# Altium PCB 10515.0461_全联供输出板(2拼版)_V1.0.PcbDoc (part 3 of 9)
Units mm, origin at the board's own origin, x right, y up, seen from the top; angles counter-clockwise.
Board outline 283.88 x 134.8 mm, 2 copper layers (Top Layer, Bottom Layer); 298 components, 0 nets, 1264 pads, 970 vias.
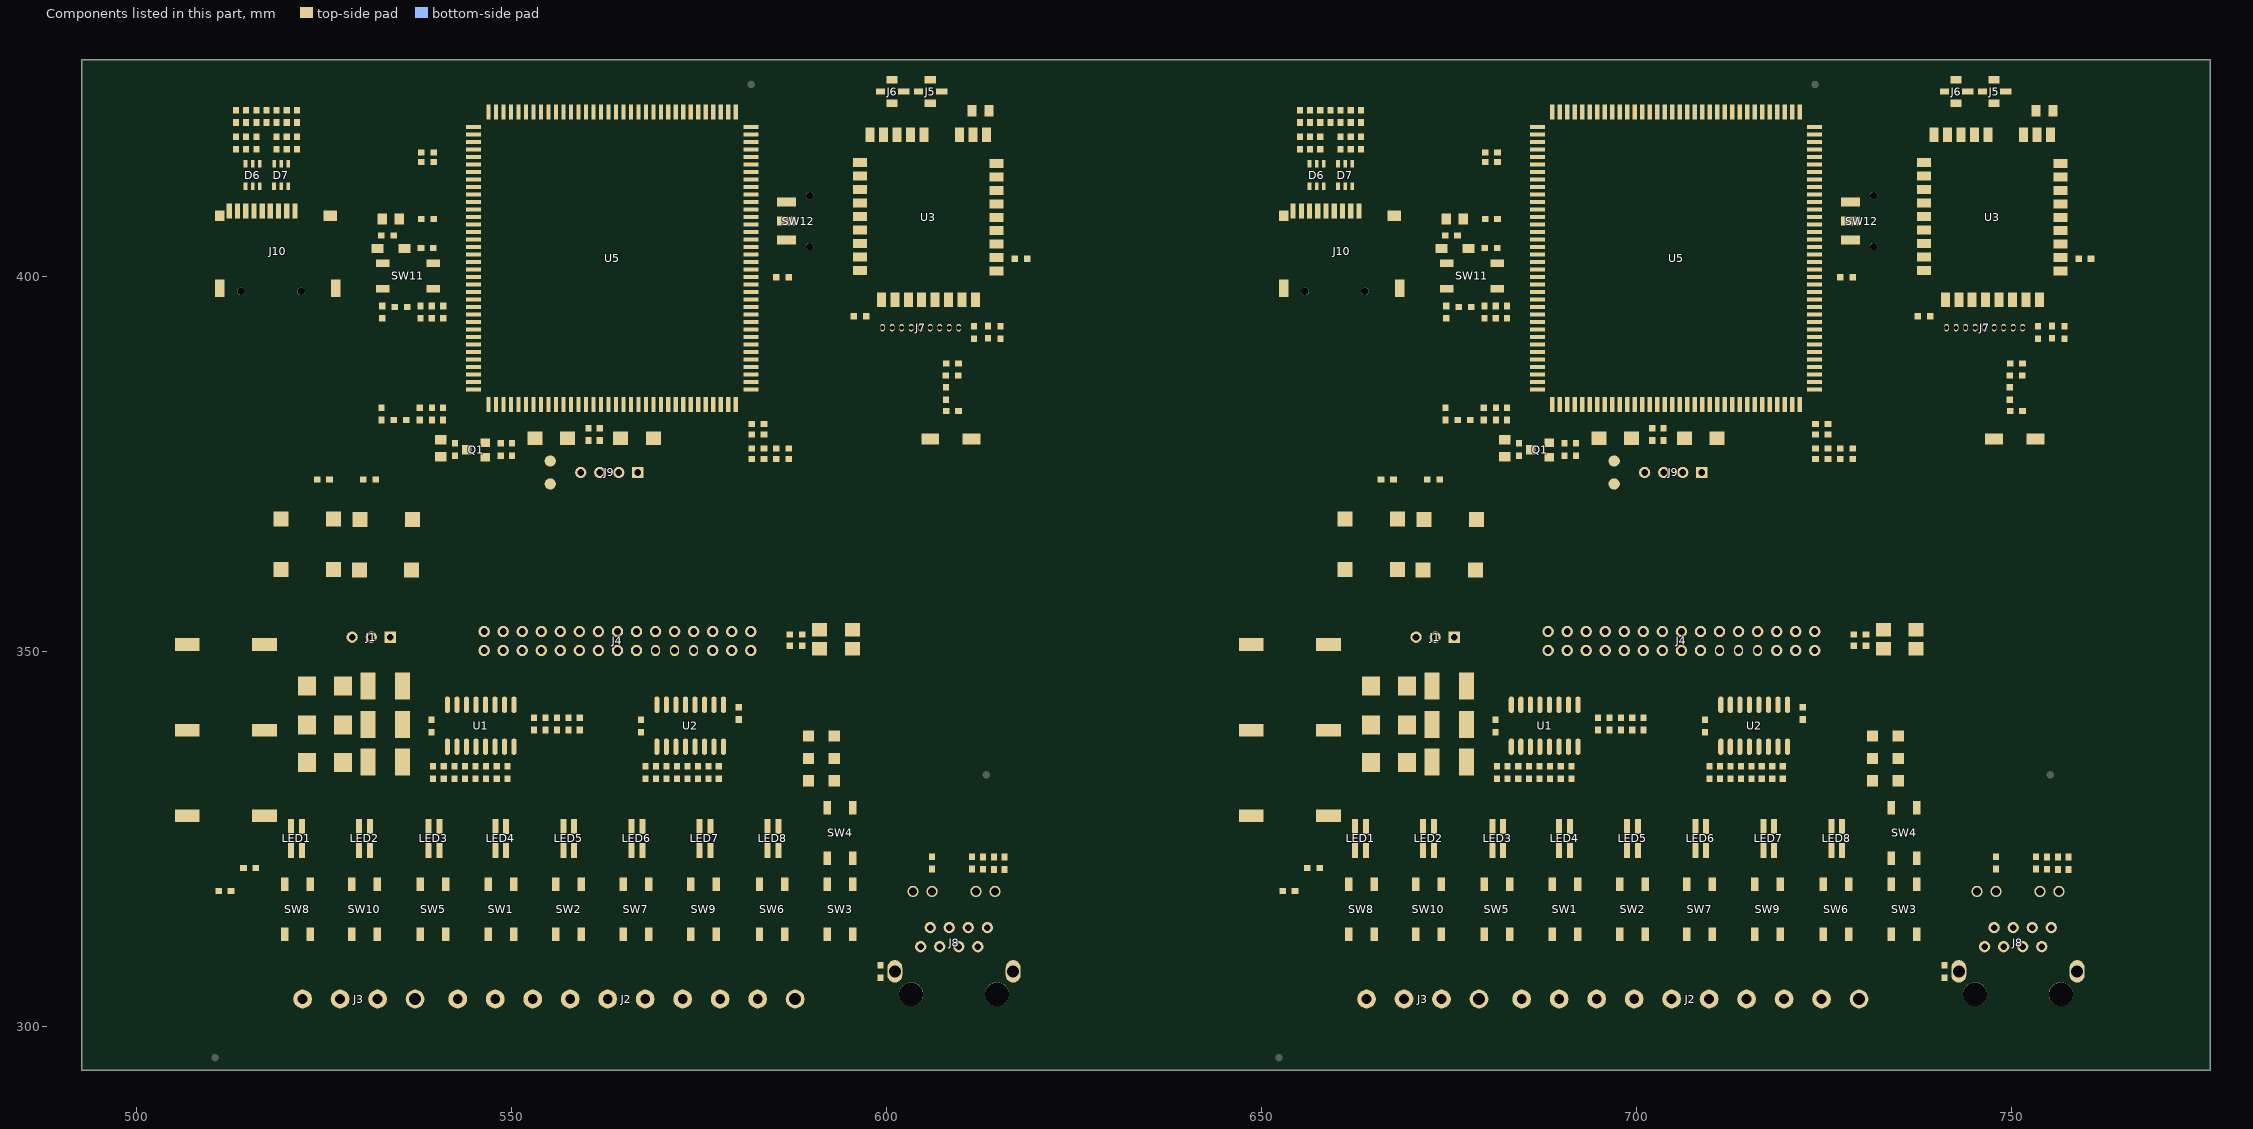
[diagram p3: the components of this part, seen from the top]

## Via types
v1: diameter 0.7, hole 0.4, Top Layer to Bottom Layer, tented both sides, 970 vias

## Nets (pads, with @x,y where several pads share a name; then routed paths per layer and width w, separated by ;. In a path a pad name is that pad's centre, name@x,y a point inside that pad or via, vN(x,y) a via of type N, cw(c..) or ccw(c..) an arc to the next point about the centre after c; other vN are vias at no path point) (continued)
copper on no net: (continued)
  Top Layer w0.3: 599.439,306.456 cw(c599.821,306.391) 599.821,306.779 ; 599.44,393.139 v1@594.868,393.139 ; 599.504,306.779 599.821,306.779 ; 599.597,308.523 ccw(c599.969,308.151) 599.442,308.151 cw(c600.736,308.151) 599.821,309.065 ; 599.849,306.807 cw(c600.486,306.169) 601.109,306.821 ; 599.855,306.496 cw(c600.442,305.908) 600.928,306.582 ; 600.066,307.024 cw(c600.698,306.391) 601.316,307.038 ; 600.226,306.841 cw(c599.821,306.867) 599.821,306.462 ; 600.327,307.285 599.821,306.779 ; 600.416,393.687 cw(c600.067,393.339) 600.56,393.339 ; 600.456,309.383 599.186,308.113 599.186,308.43 600.202,309.446 602.488,309.446 602.742,309.192 608.965,309.192 609.604,309.831 609.604,310.585 ; 600.467,306.19 ccw(c599.821,305.558) 599.821,306.462 ; 600.71,393.139 600.71,393.393 599.44,394.663 ; 600.761,396.202 cw(c599.999,395.437) 601.079,395.437 ; 601.079,396.871 601.079,395.437 ; 601.397,396.202 ccw(c602.159,395.437) 601.079,395.437 ; 601.874,393.445 ccw(c601.618,393.701) 601.98,393.701 ccw(c602.342,393.701) 602.086,393.445 ; 601.98,393.139 601.98,394.536 601.079,395.437 ; 602.554,396.203 cw(c601.785,395.435) 602.872,395.435 cw(c603.958,395.435) 603.19,396.203 ; 602.872,396.871 602.872,395.295 603.25,394.917 603.25,393.139 ; 603.144,393.445 ccw(c602.888,393.701) 603.25,393.701 ccw(c603.612,393.701) 603.356,393.445 ; 604.346,396.203 cw(c603.927,395.784) 604.52,395.784 ; 604.414,393.445 ccw(c604.158,393.701) 604.52,393.701 ccw(c604.882,393.701) 604.626,393.445 ; 604.52,393.139 604.52,396.726 ; 604.52,395.086 cw(c606.1,395.086) 604.983,396.203 ; 604.52,395.81 cw(c605.376,395.81) 604.771,396.415 ; 604.524,310.585 604.524,315.165 605.282,315.923 607.06,315.923 607.568,316.431 v1(607.568,339.418) ; 605.37,313.549 ccw(c604.345,314.574) 605.794,314.574 ccw(c607.243,314.574) 606.218,313.549 ; 605.62,318.379 ccw(c604.595,319.404) 606.044,319.404 ccw(c607.492,319.403) 606.468,318.379 ; 605.684,393.445 ccw(c605.428,393.701) 605.79,393.701 ccw(c606.152,393.701) 605.896,393.445 ; 605.79,393.139 605.79,394.79 606.457,395.457 ; 605.794,313.125 605.794,314.657 606.298,315.161 607.568,315.161 608.33,315.923 v1(608.33,338.783) ; 605.863,320.72 cw(c605.425,320.282) 606.044,320.282 cw(c606.663,320.282) 606.225,320.72 ; 606.044,317.955 606.044,320.94 ; 606.044,322.591 v1@606.87,322.591 ; 606.144,396.198 cw(c605.426,395.457) 606.457,395.457 ; 606.17,322.591 cw(c606.17,321.891) v1@606.665,322.386 ; 606.225,322.409 cw(c606.663,321.971) 606.663,322.591 cw(c606.663,323.21) 606.225,322.772 ; v1@606.411,325.716 ccw(c606.069,326.058) 606.552,326.058 ccw(c607.035,326.058) v1@606.693,325.716 ; 606.457,396.871 606.457,395.457 ; 606.771,396.198 ccw(c607.489,395.457) 606.457,395.457 ; v1@607.368,341.577 ccw(c606.885,341.577) 607.227,341.918 ccw(c607.568,342.26) v1@607.568,341.777 ; v1@607.427,339.277 cw(c607.085,338.935) 607.568,338.935 cw(c608.051,338.935) v1@607.709,339.277 ; 607.932,396.203 cw(c606.971,395.242) 608.33,395.242 ; v1@608.13,342.212 ccw(c607.647,342.212) 607.989,342.553 ccw(c608.33,342.895) v1@608.33,342.412 ; v1@608.189,338.642 cw(c607.847,338.3) 608.33,338.3 cw(c608.813,338.3) v1@608.471,338.642 ; 608.224,393.445 ccw(c607.968,393.701) 608.33,393.701 ccw(c608.692,393.701) 608.436,393.445 ; 608.25,396.871 608.33,396.791 608.33,393.139 ; 608.33,395.627 cw(c609.144,395.627) 608.568,396.203 ; v1(610.489,323.797) 613.918,323.797 614.299,323.416 614.299,322.541 615.696,322.541 ; v1@610.55,322.588 611.386,322.588 ; v1@610.63,322.386 cw(c611.12,321.896) 611.12,322.588 ; v1@610.63,323.656 cw(c610.972,323.314) 610.972,323.797 cw(c610.972,324.28) v1@610.63,323.938 ; v1(610.997,324.94) 616.585,324.94 616.966,324.559 616.966,318.717 616.204,317.955 614.434,317.955 ; v1@611.138,324.799 cw(c611.48,324.457) 611.48,324.94 cw(c611.48,325.423) v1@611.138,325.081 ; 611.204,320.718 cw(c610.767,320.28) 611.386,320.28 cw(c612.005,320.28) 611.567,320.718 ; 611.204,322.407 ccw(c610.767,321.969) 610.767,322.588 ccw(c610.767,323.207) 611.204,322.77 ; v1@611.237,319.747 ccw(c610.876,320.108) 611.386,320.108 ; v1@611.386,319.614 611.386,320.937 614.251,320.937 ; 611.386,320.07 ccw(c611.842,320.07) v1@611.519,319.747 ; 611.431,322.543 612.825,322.543 ; 611.486,418.871 611.486,418.989 ; 611.567,320.756 cw(c612.005,320.318) 612.005,320.937 cw(c612.005,321.556) 611.567,321.119 ; 611.567,322.369 cw(c611.987,321.948) 611.987,322.543 ; 611.567,322.731 ccw(c612.022,323.186) 612.022,322.543 ; 611.72,311.009 ccw(c610.695,312.034) 612.144,312.034 ccw(c613.593,312.034) 612.568,311.009 ; 611.99,318.821 ccw(c612.484,318.328) 611.894,317.955 611.894,318.725 612.521,319.352 ; 612.148,318.115 cw(c612.809,318.533) 612.256,319.087 ; 612.189,320.937 cw(c612.189,320.294) 612.644,320.749 ; 612.223,320.937 ccw(c612.223,321.532) 612.644,321.111 ; 612.401,318.276 cw(c613.134,318.739) 612.521,319.352 ; 612.644,322.362 ccw(c612.206,321.924) 612.206,322.543 ccw(c612.206,323.162) 612.644,322.724 ; 613.006,320.749 cw(c613.461,320.294) 613.461,320.937 ; 613.006,321.111 ccw(c613.427,321.532) 613.427,320.937 ; 613.657,320.937 cw(c613.657,320.286) 614.118,320.746 ; 613.703,320.937 ccw(c613.703,321.524) 614.118,321.109 ; 614.118,322.76 ccw(c613.68,323.198) 614.299,323.198 ccw(c614.918,323.198) 614.48,322.76 ; 614.48,322.359 cw(c614.918,321.922) 614.918,322.541 cw(c614.918,323.16) 614.48,322.722 ; 614.636,404.271 614.68,404.271 ; 615.369,393.148 cw(c615.807,392.71) 615.807,393.33 cw(c615.807,393.949) 615.369,393.511 ; 615.369,393.186 cw(c616.175,392.381) 616.175,393.52 ; 615.515,320.67 cw(c615.077,320.232) 615.696,320.232 cw(c616.315,320.232) 615.877,320.67 ; 615.515,322.359 ccw(c615.077,321.922) 615.077,322.541 ccw(c615.077,323.16) 615.515,322.722 ; 615.696,320.89 615.696,319.606 615.442,319.352 612.521,319.352 ; v1@616.563,404.293 v1(616.563,404.315) ; 616.905,402.471 617.043,402.333 617.347,402.029 617.347,393.849 616.827,393.33 614.807,393.33 614.997,393.33 615.188,393.52 616.712,393.52 617.093,393.901 617.093,402.283 ; 617.093,401.683 cw(c617.755,401.683) 617.287,402.152 ; 617.093,401.745 ccw(c616.517,401.745) 616.924,402.152 cw(c615.904,401.131) 617.347,401.131 ; 617.137,402.364 cw(c616.628,401.856) 617.347,401.856 ; 654.054,409.49 ccw(c653.713,409.831) 654.196,409.831 ccw(c654.679,409.831) 654.337,409.49 ; 654.196,408.698 654.196,414.58 654.599,414.983 656.382,414.983 v1@656.382,415.867 ; 654.926,418.822 ccw(c654.488,419.26) 655.107,419.26 ccw(c655.726,419.26) 655.288,418.822 ; 654.926,420.288 cw(c654.488,419.85) 655.107,419.85 cw(c655.726,419.85) 655.288,420.288 ; 654.926,422.378 ccw(c654.488,422.816) 655.107,422.816 ccw(c655.726,422.816) 655.288,422.378 ; v1@654.966,419.414 cw(c654.624,419.072) 655.107,419.072 cw(c655.59,419.072) v1@655.248,419.414 ; v1@654.966,419.696 ccw(c654.624,420.038) 655.107,420.038 ccw(c655.59,420.038) v1@655.248,419.696 ; 655.107,416.952 657.816,416.952 660.526,416.952 663.235,416.952 663.425,416.952 663.87,416.507 v1(663.87,410.538) ; 655.107,418.603 655.107,420.508 ; 655.107,422.159 655.107,425.143 v1(655.361,425.397) ; 655.107,424.301 cw(c656.457,424.301) v1@655.502,425.256 ; 655.107,425.025 cw(c655.733,425.025) v1@655.29,425.468 ; 655.158,409.49 ccw(c654.817,409.831) 655.3,409.831 ccw(c655.782,409.831) 655.441,409.49 ; 655.288,416.77 cw(c655.726,416.332) 655.726,416.952 cw(c655.726,417.571) 655.288,417.133 ; 655.3,408.698 655.3,413.398 655.742,413.84 658.028,413.84 658.282,414.094 658.282,414.983 v1@658.282,415.872 ; v1@656.109,412.81 cw(c655.461,412.162) 656.377,412.162 ; v1@656.114,415.726 cw(c655.466,415.078) 656.382,415.078 ; 656.256,409.49 ccw(c655.915,409.831) 656.398,409.831 ccw(c656.88,409.831) 656.539,409.49 ; 656.28,416.77 ccw(c655.843,416.332) 655.843,416.952 ccw(c655.843,417.571) 656.28,417.133 ; 656.28,418.822 ccw(c655.843,419.26) 656.462,419.26 ccw(c657.081,419.26) 656.643,418.822 ; 656.28,420.288 cw(c655.843,419.85) 656.462,419.85 cw(c657.081,419.85) 656.643,420.288 ; 656.28,422.378 ccw(c655.74,422.918) 656.504,422.918 ; 656.306,411.662 cw(c656.086,411.442) 656.398,411.442 ; v1@656.32,419.414 cw(c655.979,419.072) 656.462,419.072 cw(c656.945,419.072) v1@656.603,419.414 ; v1@656.32,419.696 ccw(c655.979,420.038) 656.462,420.038 ccw(c656.945,420.038) v1@656.603,419.696 ; 656.377,411.983 v1@656.377,412.951 ; 656.398,408.698 656.398,411.835 ; 656.462,418.603 656.462,420.508 ; 656.504,422.201 656.504,423.407 656.504,426.286 657.096,426.878 704.172,426.878 v1(704.637,426.413) ; 656.504,422.713 ccw(c656.978,422.713) 656.643,422.378 ; 656.643,416.77 cw(c657.081,416.332) 657.081,416.952 cw(c657.081,417.571) 656.643,417.133 ; v1@656.871,406.742 ccw(c655.365,408.248) 657.494,408.248 ; v1@657.083,406.53 ccw(c656.09,407.523) 657.494,407.523 ; v1@657.086,415.726 cw(c656.491,415.131) 657.332,415.131 ; 657.295,406.318 ccw(c656.814,406.799) 657.494,406.799 ; 657.332,411.983 657.332,410.853 657.581,410.604 ; 657.332,414.983 v1@657.332,415.811 ; 657.353,407.907 cw(c657.011,407.565) 657.494,407.565 cw(c657.977,407.565) 657.636,407.907 ; 657.494,406.601 657.494,408.698 657.494,409.548 ; 657.635,416.77 ccw(c657.197,416.332) 657.197,416.952 ccw(c657.197,417.571) 657.635,417.133 ; 657.635,418.822 ccw(c657.197,419.26) 657.816,419.26 ccw(c658.435,419.26) 657.998,418.822 ; 657.635,420.288 cw(c657.197,419.85) 657.816,419.85 cw(c658.435,419.85) 657.998,420.288 ; 657.635,422.378 ccw(c657.197,422.816) 657.816,422.816 ccw(c658.435,422.816) 657.998,422.378 ; v1@657.675,419.414 cw(c657.333,419.072) 657.816,419.072 cw(c658.299,419.072) v1@657.958,419.414 ; v1@657.675,419.696 ccw(c657.333,420.038) 657.816,420.038 ccw(c658.299,420.038) v1@657.958,419.696 ; v1@657.804,410.489 ccw(c657.581,410.332) 657.581,410.604 ; v1@657.804,410.719 cw(c657.581,410.876) 657.581,410.604 ; 657.816,418.603 657.816,420.508 ; 657.816,422.159 657.816,425.947 658.193,426.324 703.456,426.324 704.765,425.015 704.765,421.91 ; v1@657.84,410.604 657.581,410.604 ; 657.998,416.77 cw(c658.435,416.332) 658.435,416.952 cw(c658.435,417.571) 657.998,417.133 ; v1@658.058,415.726 cw(c657.516,415.184) 658.282,415.184 ; 658.282,411.983 658.846,411.983 ; 658.451,409.49 ccw(c657.496,410.444) 658.846,410.444 ; 658.663,409.277 ccw(c658.221,409.72) 658.846,409.72 ; 658.846,408.698 658.846,411.983 ; 658.99,420.288 cw(c658.552,419.85) 659.171,419.85 cw(c659.79,419.85) 659.352,420.288 ; 658.99,422.378 ccw(c658.552,422.816) 659.171,422.816 ccw(c659.79,422.816) 659.352,422.378 ; v1@659.03,415.726 cw(c658.688,415.384) 659.171,415.384 cw(c659.654,415.384) v1@659.312,415.726 ; v1@659.03,418.045 ccw(c658.688,418.387) 659.171,418.387 ccw(c659.654,418.387) v1@659.312,418.045 ; v1(659.044,425.397) 659.417,425.77 702.613,425.77 703.765,424.618 703.765,421.91 ; v1@659.044,425.597 ccw(c659.044,426.08) 659.385,425.738 ccw(c659.727,425.397) v1@659.244,425.397 ; v1@659.171,415.872 659.171,412.308 658.846,411.983 ; v1(659.171,417.904) 659.171,420.508 ; 659.171,422.159 659.171,423.492 659.933,424.254 701.384,424.254 701.765,423.873 701.765,421.91 ; 659.552,408.837 v1@659.552,410.538 ; 659.552,409.815 cw(c660.468,409.815) v1@659.82,410.463 ; 659.552,410.167 ccw(c660.51,410.167) 659.833,409.49 ; v1@660.046,413.699 cw(c659.704,413.357) 660.187,413.357 cw(c660.67,413.357) v1@660.328,413.699 ; 660.116,411.662 cw(c659.332,410.878) 660.441,410.878 ; v1(660.187,413.84) 660.187,411.983 660.441,411.729 660.441,410.157 660.79,409.807 ; 660.328,411.874 cw(c660.057,411.603) 660.441,411.603 ; 660.344,416.77 ccw(c659.907,416.332) 659.907,416.952 ccw(c659.907,417.571) 660.344,417.133 ; 660.344,418.822 ccw(c659.907,419.26) 660.526,419.26 ccw(c661.145,419.26) 660.707,418.822 ; 660.344,420.288 cw(c659.907,419.85) 660.526,419.85 cw(c661.145,419.85) 660.707,420.288 ; 660.344,422.378 ccw(c659.907,422.816) 660.526,422.816 ccw(c661.145,422.816) 660.707,422.378 ; v1@660.384,419.414 cw(c660.043,419.072) 660.526,419.072 cw(c661.009,419.072) v1@660.667,419.414 ; v1@660.384,419.696 ccw(c660.043,420.038) 660.526,420.038 ccw(c661.009,420.038) v1@660.667,419.696 ; v1@660.384,423.266 cw(c660.043,422.924) 660.526,422.924 cw(c661.009,422.924) v1@660.667,423.266 ; 660.526,418.603 660.526,420.508 ; 660.526,422.159 v1(660.526,423.407) ; 660.654,409.495 ccw(c660.363,409.807) 660.79,409.807 ; 660.674,409.924 cw(c660.146,409.397) 660.89,409.341 ; 660.707,416.77 cw(c661.145,416.332) 661.145,416.952 cw(c661.145,417.571) 660.707,417.133 ; 660.79,408.698 660.79,409.807 ; 660.927,409.495 cw(c661.218,409.807) 660.79,409.807 ; v1@660.935,413.346 ccw(c660.434,413.847) 661.142,413.847 ; v1(660.949,425.016) 702.097,425.016 702.765,424.348 702.765,421.91 ; v1@661.09,424.875 cw(c661.432,424.533) 661.432,425.016 cw(c661.432,425.499) v1@661.09,425.157 ; v1@661.142,410.604 661.142,411.983 ; 661.142,411.168 ccw(c661.833,411.168) v1@661.344,410.679 ; v1@661.142,413.271 661.142,414.983 ; 661.699,416.77 ccw(c661.261,416.332) 661.261,416.952 ccw(c661.261,417.571) 661.699,417.133 ; 661.699,418.822 ccw(c661.261,419.26) 661.88,419.26 ccw(c662.499,419.26) 662.062,418.822 ; 661.699,420.288 cw(c661.261,419.85) 661.88,419.85 cw(c662.499,419.85) 662.062,420.288 ; 661.699,422.378 ccw(c661.261,422.816) 661.88,422.816 ccw(c662.499,422.816) 662.062,422.378 ; v1@661.739,419.414 cw(c661.397,419.072) 661.88,419.072 cw(c662.363,419.072) v1@662.022,419.414 ; v1@661.739,419.696 ccw(c661.397,420.038) 661.88,420.038 ccw(c662.363,420.038) v1@662.022,419.696 ; v1@661.739,423.308 cw(c661.397,422.967) 661.88,422.967 cw(c662.363,422.967) v1@662.022,423.308 ; 661.746,409.488 ccw(c660.909,410.324) 662.092,410.324 ; 661.88,418.603 661.88,420.508 ; 661.88,422.159 v1(661.88,423.45) ; 661.887,408.696 661.887,409.444 662.092,409.649 662.092,411.983 v1(662.092,413.586) ; v1@661.951,413.445 cw(c661.609,413.103) 662.092,413.103 cw(c662.575,413.103) v1@662.233,413.445 ; v1@661.951,415.731 cw(c661.609,415.389) 662.092,415.389 cw(c662.575,415.389) v1@662.233,415.731 ; 662.062,416.77 cw(c662.499,416.332) 662.499,416.952 cw(c662.499,417.571) 662.062,417.133 ; 662.092,414.633 cw(c662.092,413.788) 662.689,414.386 ; v1(662.092,415.872) 662.092,414.983 662.987,414.088 662.987,408.698 ; 662.296,327.393 ccw(c661.869,327.82) 662.473,327.82 ccw(c663.077,327.82) 662.65,327.393 ; 662.473,326.235 662.473,330.782 663.165,331.474 681.072,331.474 681.396,331.798 681.396,333.005 ; v1(662.473,427.683) 662.592,427.564 704.629,427.564 705.765,426.428 705.765,421.91 ; v1@662.614,427.824 ccw(c663.243,428.453) 663.243,427.564 ; 662.845,409.49 ccw(c662.504,409.831) 662.987,409.831 ccw(c663.469,409.831) 663.128,409.49 ; 663.054,416.77 ccw(c662.616,416.332) 662.616,416.952 ccw(c662.616,417.571) 663.054,417.133 ; 663.054,418.822 ccw(c662.616,419.26) 663.235,419.26 ccw(c663.854,419.26) 663.416,418.822 ; 663.054,420.288 cw(c662.616,419.85) 663.235,419.85 cw(c663.854,419.85) 663.416,420.288 ; 663.054,422.378 ccw(c662.616,422.816) 663.235,422.816 ccw(c663.854,422.816) 663.416,422.378 ; v1@663.094,419.414 cw(c662.752,419.072) 663.235,419.072 cw(c663.718,419.072) v1@663.376,419.414 ; v1@663.094,419.696 ccw(c662.752,420.038) 663.235,420.038 ccw(c663.718,420.038) v1@663.376,419.696 ; v1@663.094,423.351 cw(c662.752,423.009) 663.235,423.009 cw(c663.718,423.009) v1@663.376,423.351 ; 663.235,418.603 663.235,420.508 ; 663.235,422.159 v1(663.235,423.492) ; v1@663.729,410.679 ccw(c663.387,411.021) 663.87,411.021 ccw(c664.353,411.021) v1@664.011,410.679 ; 663.756,327.368 ccw(c663.329,327.795) 663.933,327.795 ccw(c664.537,327.795) 664.11,327.368 ; v1(663.87,428.318) 705.399,428.318 706.765,426.952 706.765,421.91 ; 663.933,326.21 663.933,330.21 664.643,330.92 682.55,330.92 682.811,331.181 682.811,333.005 ; 664.986,312.243 v1(668.823,312.243) ; 665.233,311.995 cw(c665.831,311.398) 665.831,312.243 cw(c665.831,313.088) 665.233,312.49 ; v1@668.682,312.101 ccw(c668.34,311.76) 668.34,312.243 ccw(c668.34,312.726) v1@668.682,312.384 ; 670.025,309.192 670.533,309.7 ; 670.285,311.595 cw(c669.688,310.998) 670.533,310.998 cw(c671.378,310.998) 670.78,311.595 ; 670.285,319.59 ccw(c669.688,320.188) 670.533,320.188 ccw(c671.378,320.188) 670.78,319.59 ; v1@670.392,320.286 cw(c670.05,319.944) 670.533,319.944 cw(c671.016,319.944) v1@670.674,320.286 ; 670.533,309.26 670.533,309.7 ; 670.533,312.243 670.533,309.7 ; 670.533,318.943 v1(670.533,320.427) ; 670.982,309.251 670.533,309.7 ; 671.368,327.393 ccw(c670.941,327.82) 671.544,327.82 ccw(c672.148,327.82) 671.721,327.393 ; 671.544,326.235 671.544,329.82 672.09,330.366 683.901,330.366 684.226,330.691 684.226,333.005 ; 672.828,327.368 ccw(c672.401,327.795) 673.004,327.795 ccw(c673.608,327.795) 673.181,327.368 ; 673.004,326.21 673.004,329.248 673.568,329.812 685.252,329.812 685.641,330.201 685.641,333.005 ; 673.685,319.59 ccw(c673.088,320.188) 673.933,320.188 ccw(c674.778,320.188) 674.18,319.59 ; 673.933,318.943 673.933,321.541 674.376,321.984 692.029,321.984 692.388,322.343 692.388,334.916 693.588,336.116 702.986,336.116 703.359,336.489 703.359,346.608 703.446,346.695 703.446,350.086 ; v1(675.046,321.003) 675.473,321.43 692.258,321.43 692.942,322.114 692.942,334.2 693.969,335.227 703.367,335.227 703.913,335.773 703.913,346.378 704.764,347.229 704.764,351.404 705.986,352.626 ; v1@675.046,321.203 ccw(c675.046,321.686) 675.387,321.344 ccw(c675.729,321.003) v1@675.246,321.003 ; v1(675.3,312.243) 679.683,312.243 ; v1@675.441,312.101 cw(c675.783,311.76) 675.783,312.243 cw(c675.783,312.726) v1@675.441,312.384 ; 679.436,311.995 ccw(c678.838,311.398) 678.838,312.243 ccw(c678.838,313.088) 679.436,312.49 ; 679.589,403.938 ccw(c679.151,404.376) 679.77,404.376 ccw(c680.389,404.376) 679.952,403.938 ; 679.627,415.056 cw(c679.189,414.618) 679.808,414.618 cw(c680.428,414.618) 679.99,415.056 ; 679.627,415.418 ccw(c679.189,415.856) 679.808,415.856 ccw(c680.428,415.856) 679.99,415.418 ; 679.627,416.326 cw(c679.189,415.888) 679.808,415.888 cw(c680.428,415.888) 679.99,416.326 ; 679.683,319.544 681.015,320.876 692.572,320.876 693.496,321.8 693.496,333.484 694.477,334.465 703.748,334.465 704.467,335.184 704.467,346.149 705.986,347.668 705.986,350.086 ; 679.683,319.693 ccw(c679.683,320.051) 679.937,319.798 ; 679.77,403.757 679.77,405.61 680.07,405.91 686.765,405.91 ; 679.808,416.507 679.808,414.158 680.126,413.84 682.666,413.84 683.736,414.91 686.765,414.91 688.327,414.91 688.635,414.602 688.635,385.91 ; 680.033,319.343 cw(c681.365,319.343) 680.423,320.284 ; 680.616,326.616 680.616,328.859 681.015,329.258 686.603,329.258 687.057,329.712 687.057,333.005 ; 680.616,328.17 ccw(c681.715,328.17) 680.938,327.393 ; 681.215,332.785 cw(c680.777,332.347) 681.396,332.347 cw(c682.015,332.347) 681.577,332.785 ; 681.236,334.894 ccw(c680.969,335.227) 681.396,335.227 ; 681.24,403.938 ccw(c680.802,404.376) 681.421,404.376 ccw(c682.04,404.376) 681.603,403.938 ; 681.352,334.694 cw(c682.535,334.694) 681.699,335.53 ; 681.396,334.656 681.396,335.227 ; 681.421,403.757 681.421,404.467 681.864,404.91 686.765,404.91 688.548,404.91 ; 681.459,407.617 682.166,406.91 686.765,406.91 ; 681.459,415.237 682.539,415.237 683.212,415.91 686.765,415.91 ; 681.459,416.507 681.862,416.91 686.765,416.91 ; 681.467,416.538 cw(c682.365,415.639) 682.365,416.91 ; 681.498,407.361 cw(c681.498,406.834) 681.87,407.206 ; 681.556,334.894 cw(c681.823,335.227) 681.396,335.227 ; 681.652,334.694 cw(c683.559,334.694) 682.211,336.042 ; 681.679,415.056 cw(c682.117,414.618) 682.117,415.237 cw(c682.117,415.856) 681.679,415.418 ; 681.679,416.326 cw(c683.09,414.915) 683.09,416.91 ; 681.754,407.617 ccw(c682.465,407.617) 681.962,407.114 ; 682.076,326.591 682.076,328.287 682.412,328.623 688,328.623 688.472,329.095 688.472,333.005 ; 682.076,328.145 ccw(c683.175,328.145) 682.398,327.368 ; 682.63,332.785 cw(c682.192,332.347) 682.811,332.347 cw(c683.43,332.347) 682.992,332.785 ; 682.63,334.875 ccw(c681.01,336.495) 683.301,336.495 ; 682.811,334.656 683.301,335.145 ; 682.816,334.95 ccw(c682.829,335.617) 683.301,335.145 ; 682.842,334.663 ccw(c681.734,335.771) 683.301,335.771 ; 683.054,334.451 ccw(c682.458,335.047) 683.301,335.047 ; 683.068,334.694 cw(c683.595,334.694) 683.222,335.066 ; 683.083,312.243 688.732,312.243 ; 683.16,336.368 cw(c682.818,336.026) 683.301,336.026 cw(c683.784,336.026) 683.442,336.368 ; 683.301,337.259 683.301,335.145 ; 683.331,311.995 cw(c683.928,311.398) 683.928,312.243 cw(c683.928,313.088) 683.331,312.49 ; 684.045,332.785 cw(c683.607,332.347) 684.226,332.347 cw(c684.845,332.347) 684.408,332.785 ; 684.045,334.875 ccw(c682.775,336.145) 684.571,336.145 ; 684.226,334.656 684.571,335 684.571,337.259 ; 684.257,334.663 ccw(c683.499,335.421) 684.571,335.421 ; 684.43,336.368 cw(c684.088,336.026) 684.571,336.026 cw(c685.054,336.026) 684.712,336.368 ; 684.43,341.956 cw(c684.088,341.614) 684.571,341.614 cw(c685.054,341.614) 684.712,341.956 ; 684.571,342.847 684.571,340.561 682.285,338.275 682.285,336.116 681.396,335.227 ; 685.46,332.785 cw(c685.022,332.347) 685.641,332.347 cw(c686.26,332.347) 685.823,332.785 ; 685.46,334.875 ccw(c684.541,335.794) 685.841,335.794 ; 685.672,334.663 ccw(c685.265,335.07) 685.841,335.07 ; 685.7,336.368 cw(c685.358,336.026) 685.841,336.026 cw(c686.324,336.026) 685.982,336.368 ; 685.841,334.855 685.841,337.259 ; 685.952,404.822 ccw(c685.738,404.608) 685.738,404.91 ccw(c685.738,405.212) 685.952,404.998 ; 685.952,405.822 ccw(c685.738,405.608) 685.738,405.91 ccw(c685.738,406.212) 685.952,405.998 ; 685.952,406.822 ccw(c685.738,406.608) 685.738,406.91 ccw(c685.738,407.212) 685.952,406.998 ; 685.952,414.822 ccw(c685.738,414.608) 685.738,414.91 ccw(c685.738,415.212) 685.952,414.998 ; 685.952,415.822 ccw(c685.738,415.608) 685.738,415.91 ccw(c685.738,416.212) 685.952,415.998 ; 685.952,416.822 ccw(c685.738,416.608) 685.738,416.91 ccw(c685.738,417.212) 685.952,416.998 ; v1@686.476,382.471 686.476,383.36 ; 686.476,383.233 686.476,383.36 ; 686.476,383.911 cw(c687.764,383.911) 686.853,384.822 ccw(c687.067,384.608) 686.765,384.608 ccw(c686.463,384.608) 686.677,384.822 ; 686.476,384.635 cw(c687.04,384.635) 686.641,385.034 ; 686.536,384.69 cw(c686.765,384.461) 686.765,384.785 ; v1@686.547,382.527 ccw(c686.02,383.054) 686.765,383.054 ; 686.558,384.712 ccw(c686.36,384.91) 686.64,384.91 ; v1@686.603,382.471 686.765,382.633 686.765,384.91 ; v1@686.617,382.739 cw(c686.959,383.081) 686.476,383.081 cw(c685.993,383.081) 686.335,382.739 ccw(c685.295,383.779) 686.765,383.779 ; 686.765,385.91 688.635,385.91 ; 686.765,388.91 688.597,388.91 ; 686.765,391.91 688.594,391.91 ; 686.765,394.91 688.628,394.91 ; 686.765,397.91 688.563,397.91 ; 686.875,332.785 cw(c686.438,332.347) 687.057,332.347 cw(c687.676,332.347) 687.238,332.785 ; 686.875,334.875 ccw(c686.306,335.444) 687.111,335.444 ; 686.97,336.368 cw(c686.628,336.026) 687.111,336.026 cw(c687.594,336.026) 687.252,336.368 ; 687.111,334.71 687.111,337.259 ; 687.111,335.181 ccw(c687.544,335.181) 687.238,334.875 ; 687.578,384.822 cw(c687.792,384.608) 687.792,384.91 cw(c687.792,385.212) 687.578,384.998 ; 687.578,385.822 cw(c687.792,385.608) 687.792,385.91 cw(c687.792,386.212) 687.578,385.998 ; 687.578,388.822 cw(c687.792,388.608) 687.792,388.91 cw(c687.792,389.212) 687.578,388.998 ; 687.578,391.822 cw(c687.792,391.608) 687.792,391.91 cw(c687.792,392.212) 687.578,391.998 ; 687.578,394.822 cw(c687.792,394.608) 687.792,394.91 cw(c687.792,395.212) 687.578,394.998 ; 687.578,397.822 cw(c687.792,397.608) 687.792,397.91 cw(c687.792,398.212) 687.578,397.998 ; 687.578,404.822 cw(c687.792,404.608) 687.792,404.91 cw(c687.792,405.212) 687.578,404.998 ; 687.578,414.822 cw(c687.792,414.608) 687.792,414.91 cw(c687.792,415.212) 687.578,414.998 ; 688.24,336.368 cw(c687.898,336.026) 688.381,336.026 cw(c688.864,336.026) 688.522,336.368 ; 688.24,343.738 ccw(c687.898,344.08) 688.381,344.08 ccw(c688.864,344.08) 688.522,343.738 ; v1@688.24,344.23 cw(c687.898,343.888) 688.381,343.888 cw(c688.864,343.888) v1@688.522,344.23 ; 688.254,380.82 688.762,381.328 688.762,381.455 ; 688.29,332.785 cw(c687.853,332.347) 688.472,332.347 cw(c689.091,332.347) 688.653,332.785 ; 688.29,334.875 ccw(c688.072,335.094) 688.381,335.094 ; 688.381,334.746 688.381,337.259 ; 688.381,335.532 ccw(c689.31,335.532) 688.653,334.875 ; 688.381,342.847 v1(688.381,344.371) ; 688.485,311.995 ccw(c687.887,311.398) 687.887,312.243 ccw(c687.887,313.088) 688.485,312.49 ; 688.677,382.097 cw(c688.47,381.89) 688.762,381.89 ; 688.732,318.943 688.732,319.322 689.732,320.322 692.907,320.322 694.05,321.465 694.05,333.149 694.477,333.576 698.16,333.576 703.875,333.576 705.021,334.722 705.021,345.919 707.152,348.05 707.152,351.252 708.526,352.626 ; 688.732,319.693 ccw(c688.732,320.588) 689.365,319.955 ; 688.762,381.201 688.762,381.455 ; 688.762,381.876 cw(c689.074,381.876) 688.853,382.097 ; 688.765,382.91 688.762,382.907 688.762,381.455 ; 688.775,381.214 689.765,381.214 ; 689.082,319.343 cw(c689.877,319.343) 689.315,319.905 ; 689.51,336.368 cw(c689.168,336.026) 689.651,336.026 cw(c690.134,336.026) 689.792,336.368 ; 689.51,343.738 ccw(c689.168,344.08) 689.651,344.08 ccw(c690.134,344.08) 689.792,343.738 ; 689.511,327.393 ccw(c688.602,328.301) 689.887,328.301 ; 689.651,334.891 689.651,337.259 ; 689.651,335.158 ccw(c690.351,335.158) 689.856,334.663 ; 689.651,335.882 ccw(c691.075,335.882) 690.068,334.875 ; 689.651,342.847 689.651,344.752 v1(690.159,345.26) ; 689.687,327.317 689.687,326.616 689.887,326.816 689.887,333.005 ; 689.706,332.785 cw(c689.268,332.347) 689.887,332.347 cw(c690.506,332.347) 690.068,332.785 ; 689.723,327.181 ccw(c689.326,327.577) 689.887,327.577 ; 689.765,380.82 689.863,380.722 690.765,380.722 690.765,382.91 ; v1@689.959,345.26 cw(c689.476,345.26) 689.818,344.919 cw(c690.159,344.577) v1@690.159,345.06 ; v1@690.526,385.769 ccw(c690.184,385.427) 690.184,385.91 ccw(c690.184,386.393) v1@690.526,386.051 ; 690.677,382.097 cw(c690.463,381.883) 690.765,381.883 cw(c691.067,381.883) 690.853,382.097 ; 690.78,336.368 cw(c690.438,336.026) 690.921,336.026 cw(c691.404,336.026) 691.062,336.368 ; v1@690.808,385.769 cw(c691.15,385.427) 691.15,385.91 cw(c691.15,386.393) v1@690.808,386.051 ; 690.921,335.036 690.921,337.259 ; 690.921,335.508 ccw(c692.117,335.508) 691.271,334.663 ; 690.921,336.232 ccw(c692.841,336.232) 691.483,334.875 ; 690.971,327.368 ccw(c690.17,328.168) 691.302,328.168 ; 691.121,332.785 cw(c690.683,332.347) 691.302,332.347 cw(c691.921,332.347) 691.483,332.785 ; 691.147,327.254 691.147,326.591 691.302,326.746 691.302,333.005 ; 692.132,312.243 697.781,312.243 697.781,311.73 ; 692.132,318.531 694.604,321.003 694.604,332.433 694.985,332.814 704.383,332.814 705.575,334.006 705.575,345.69 708.526,348.641 708.526,350.086 ; 692.38,311.995 cw(c692.977,311.398) 692.977,312.243 cw(c692.977,313.088) 692.38,312.49 ; v1@693.447,313.143 ccw(c693.105,313.485) 693.588,313.485 ccw(c694.071,313.485) v1@693.729,313.143 ; v1(693.588,313.002) 693.588,319.204 695.158,320.774 695.158,331.463 695.755,332.06 705.026,332.06 706.129,333.163 706.129,345.461 709.717,349.049 709.717,353.515 709.328,353.904 704.518,353.904 ; v1@694.336,313.651 ccw(c693.994,313.993) 694.477,313.993 ccw(c694.96,313.993) v1@694.618,313.651 ; v1@694.477,313.637 694.477,319.309 695.763,320.595 695.763,330.925 696.344,331.506 705.488,331.506 706.683,332.701 706.683,345.231 709.298,347.846 713.192,347.846 713.606,348.26 713.606,350.086 ; 694.677,339.262 cw(c694.239,338.824) 694.858,338.824 cw(c695.477,338.824) 695.039,339.262 ; 694.858,336.116 694.858,339.482 ; 694.96,378.407 694.96,378.661 ; v1@695.352,313.143 ccw(c695.01,313.485) 695.493,313.485 ccw(c695.976,313.485) v1@695.634,313.143 ; v1@695.352,385.769 ccw(c695.01,385.427) 695.01,385.91 ccw(c695.01,386.393) v1@695.352,386.051 ; v1(695.493,313.002) 695.493,319.542 696.382,320.431 696.382,330.346 696.988,330.952 705.95,330.952 707.237,332.239 707.237,345.002 709.527,347.292 719.369,347.292 720.004,347.927 720.004,351.308 718.686,352.626 ; v1@695.634,385.769 cw(c695.976,385.427) 695.976,385.91 cw(c695.976,386.393) v1@695.634,386.051 ; 696.201,339.262 cw(c695.763,338.824) 696.382,338.824 cw(c697.001,338.824) 696.563,339.262 ; v1@696.241,313.651 ccw(c695.899,313.993) 696.382,313.993 ccw(c696.865,313.993) v1@696.523,313.651 ; v1@696.241,335.086 ccw(c695.899,334.744) 695.899,335.227 ccw(c695.899,335.71) v1@696.241,335.368 ; v1@696.241,338.416 ccw(c695.899,338.758) 696.382,338.758 ccw(c696.865,338.758) v1@696.523,338.416 ; v1@696.382,313.637 696.382,319.606 697.002,320.226 697.002,329.57 697.83,330.398 706.793,330.398 707.791,331.396 707.791,344.772 709.757,346.738 720.339,346.738 721.226,347.625 721.226,350.086 ; v1(696.382,338.275) 696.382,339.482 ; v1@696.523,335.086 cw(c696.865,334.744) 696.865,335.227 cw(c696.865,335.71) v1@696.523,335.368 ; 697.017,372.438 703.367,372.438 703.621,372.692 ; 697.017,375.359 698.795,375.359 699.328,375.892 699.328,378.09 ; 697.229,372.099 cw(c698.048,371.28) 698.048,372.438 ; 697.441,371.887 cw(c698.772,370.556) 698.772,372.438 ; 697.441,372.735 ccw(c698.159,373.453) 698.159,372.438 ; 697.441,374.935 cw(c698.466,373.91) 698.466,375.359 cw(c698.466,376.808) 697.441,375.783 ; 697.533,311.995 ccw(c696.936,311.398) 696.936,312.243 ccw(c696.936,313.088) 697.533,312.49 ; 697.725,339.262 cw(c697.287,338.824) 697.906,338.824 cw(c698.525,338.824) 698.087,339.262 ; v1@697.765,334.324 ccw(c697.423,333.982) 697.423,334.465 ccw(c697.423,334.948) v1@697.765,334.606 ; v1@697.765,338.416 ccw(c697.423,338.758) 697.906,338.758 ccw(c698.389,338.758) v1@698.047,338.416 ; 697.781,318.943 697.781,319.35 ; v1(697.906,338.275) 697.906,339.482 ; v1@698.047,334.324 cw(c698.389,333.982) 698.389,334.465 cw(c698.389,334.948) v1@698.047,334.606 ; 698.366,352.626 700.906,352.626 ; 698.582,327.393 ccw(c698.155,327.82) 698.759,327.82 ccw(c699.362,327.82) 698.935,327.393 ; 698.625,385.91 ccw(c698.625,386.489) v1@699.035,386.08 ; 698.759,326.235 698.759,326.616 698.759,329.603 699,329.844 708.779,329.844 709.717,330.782 709.717,333.005 ; 698.761,385.91 cw(c698.761,385.523) v1@699.035,385.797 ; v1(698.795,314.272) 700.7,314.272 ; 698.798,377.877 cw(c697.517,376.596) 699.328,376.596 cw(c701.139,376.596) 699.858,377.877 ; 698.799,352.193 cw(c699.843,351.149) 699.843,352.626 cw(c699.843,354.104) 698.799,353.059 ; v1@698.936,314.131 cw(c699.278,313.789) 699.278,314.272 cw(c699.278,314.755) v1@698.936,314.413 ; 699.01,378.089 cw(c698.242,377.321) 699.328,377.321 cw(c700.414,377.321) 699.646,378.089 ; 699.249,339.262 cw(c698.811,338.824) 699.43,338.824 cw(c700.049,338.824) 699.611,339.262 ; v1@699.289,333.435 ccw(c698.947,333.093) 698.947,333.576 ccw(c698.947,334.059) v1@699.289,333.717 ; v1@699.289,338.416 ccw(c698.947,338.758) 699.43,338.758 ccw(c699.913,338.758) v1@699.571,338.416 ; v1@699.317,385.797 cw(c699.591,385.523) 699.591,385.91 ; v1@699.317,386.08 ccw(c699.727,386.489) 699.727,385.91 ; v1(699.43,338.275) 699.43,339.482 ; v1@699.571,333.435 cw(c699.913,333.093) 699.913,333.576 cw(c699.913,334.059) v1@699.571,333.717 ; 700.042,327.368 ccw(c699.615,327.795) 700.219,327.795 ccw(c700.822,327.795) 700.395,327.368 ; 700.219,326.21 700.219,326.591 700.219,329.071 700.438,329.29 710.384,329.29 711.114,330.02 711.114,333.005 ; 700.473,352.193 ccw(c699.428,351.149) 699.428,352.626 ccw(c699.428,354.104) 700.473,353.059 ; 700.677,421.097 cw(c700.463,420.883) 700.765,420.883 cw(c701.067,420.883) 700.853,421.097 ; 700.765,421.91 700.765,418.347 701.202,417.91 719.765,417.91 ; 700.773,339.262 cw(c700.335,338.824) 700.954,338.824 cw(c701.573,338.824) 701.135,339.262 ; v1@700.813,332.673 ccw(c700.471,332.331) 700.471,332.814 ccw(c700.471,333.297) v1@700.813,332.955 ; v1@700.813,338.416 ccw(c700.471,338.758) 700.954,338.758 ccw(c701.437,338.758) v1@701.095,338.416 ; v1(700.954,338.275) 700.954,339.482 ; v1@701.095,332.673 cw(c701.437,332.331) 701.437,332.814 cw(c701.437,333.297) v1@701.095,332.955 ; 701.181,313.891 700.8,314.272 ; 701.181,314.272 700.7,314.272 ; 701.181,314.653 700.8,314.272 ; 701.181,318.943 701.181,319.325 702.26,320.404 714.761,320.404 715.777,319.388 715.777,318.943 ; 701.181,319.693 ccw(c701.181,320.581) 701.809,319.953 ; 701.531,319.343 cw(c702.332,319.343) 701.766,319.91 ; 701.677,383.723 ccw(c701.463,383.937) 701.765,383.937 ccw(c702.067,383.937) 701.853,383.723 ; 701.677,422.723 ccw(c701.463,422.937) 701.765,422.937 ccw(c702.067,422.937) 701.853,422.723 ; 701.69,384.91 686.765,384.91 ; 701.765,382.91 701.765,385.861 ; 701.916,377.87 cw(c701.478,377.432) 702.097,377.432 cw(c702.716,377.432) 702.278,377.87 ; 702.097,375.994 702.097,378.09 ; 702.097,379.741 702.765,380.409 702.765,382.91 ; 702.097,380.035 ccw(c702.097,380.746) 702.6,380.243 ; 702.353,379.779 cw(c702.88,379.779) 702.508,380.151 ; 702.677,382.097 cw(c702.463,381.883) 702.765,381.883 cw(c703.067,381.883) 702.853,382.097 ; 702.677,422.723 ccw(c702.463,422.937) 702.765,422.937 ccw(c703.067,422.937) 702.853,422.723 ; 703.013,349.653 cw(c701.968,348.609) 703.446,348.609 cw(c704.923,348.609) 703.879,349.653 ; 703.28,373.341 cw(c702.832,372.692) 703.621,372.692 ; 703.44,377.87 cw(c703.002,377.432) 703.621,377.432 cw(c704.24,377.432) 703.802,377.87 ; 703.44,379.96 ccw(c702.654,380.745) 703.765,380.745 ; 703.446,352.626 703.446,352.832 704.518,353.904 ; 703.446,353.238 ccw(c703.446,354.218) 704.139,353.525 ; 703.677,382.097 cw(c703.463,381.883) 703.765,381.883 cw(c704.067,381.883) 703.853,382.097 ; 703.677,422.723 ccw(c703.463,422.937) 703.765,422.937 ccw(c704.067,422.937) 703.853,422.723 ; 703.713,378.09 ccw(c703.713,380.984) 705.76,378.937 ; 703.757,352.648 cw(c704.772,352.719) 704.053,353.439 ; 703.765,379.885 703.765,382.91 ; 703.802,377.908 cw(c704.24,377.47) 704.24,378.09 cw(c704.24,378.709) 703.802,378.271 ; 703.962,373.341 ccw(c704.41,372.692) 703.621,372.692 ; 704.056,352.669 cw(c705.641,352.78) 704.518,353.904 ; 704.437,378.09 ccw(c704.437,380.26) 705.972,378.725 ; v1@704.437,426.413 ccw(c703.954,426.413) 704.296,426.754 ccw(c704.637,427.096) v1@704.637,426.613 ; v1@704.624,384.742 cw(c704.282,384.4) 704.765,384.4 cw(c705.248,384.4) v1@704.906,384.742 ; 704.677,383.723 ccw(c704.463,383.937) 704.765,383.937 ccw(c705.067,383.937) 704.853,383.723 ; 704.677,422.723 ccw(c704.463,422.937) 704.765,422.937 ccw(c705.067,422.937) 704.853,422.723 ; 704.677,303.604 704.677,308.095 705.145,308.563 732.329,308.563 734.355,310.589 738.165,310.589 738.8,311.224 738.8,330.909 738.292,331.417 731.815,331.417 731.46,331.772 ; 704.765,382.91 v1(704.765,384.883) ; 705.161,378.09 ccw(c705.161,379.536) 706.184,378.513 ; 705.246,378.09 cw(c705.246,377.363) 705.76,377.877 ; 705.374,352.626 cw(c703.896,352.626) 704.941,351.581 cw(c705.986,350.536) 705.986,352.014 ; 705.553,349.653 cw(c704.508,348.609) 705.986,348.609 cw(c707.463,348.609) 706.419,349.653 ; 705.677,422.723 ccw(c705.463,422.937) 705.765,422.937 ccw(c706.067,422.937) 705.853,422.723 ; 706.072,378.09 703.621,378.09 703.621,373.835 703.621,372.692 ; 706.677,382.097 cw(c706.463,381.883) 706.765,381.883 cw(c707.067,381.883) 706.853,382.097 ; 706.677,422.723 ccw(c706.463,422.937) 706.765,422.937 ccw(c707.067,422.937) 706.853,422.723 ; 706.765,382.91 706.765,380.724 707.685,379.804 713.4,379.804 713.781,379.423 713.781,376.248 714.416,375.613 723.877,375.613 ; 707.653,327.393 ccw(c707.227,327.82) 707.83,327.82 ccw(c708.434,327.82) 708.007,327.393 ; 707.677,382.097 cw(c707.463,381.883) 707.765,381.883 cw(c708.067,381.883) 707.853,382.097 ; 707.677,421.097 cw(c707.463,420.883) 707.765,420.883 cw(c708.067,420.883) 707.853,421.097 ; 707.765,382.91 707.765,381.248 708.447,380.566 714.035,380.566 714.416,380.185 714.416,377.518 714.924,377.01 723.877,377.01 ; 707.765,417.99 707.765,421.91 ; 707.83,326.235 707.83,326.616 707.83,328.26 708.193,328.623 711.622,328.623 712.511,329.512 712.511,333.005 ; 707.866,417.91 ccw(c707.866,418.806) v1@708.5,418.172 ; 707.914,352.626 cw(c706.436,352.626) 707.481,351.581 cw(c708.526,350.536) 708.526,352.014 ; 708.1,349.646 cw(c707.126,348.641) 708.526,348.641 cw(c709.926,348.641) 708.952,349.646 ; 708.677,382.097 cw(c708.463,381.883) 708.765,381.883 cw(c709.067,381.883) 708.853,382.097 ; 708.765,382.91 708.765,381.518 709.082,381.201 714.924,381.201 715.178,380.947 715.178,378.28 715.559,377.899 v1(729.783,377.899) ; v1@708.783,418.172 ccw(c709.416,418.806) 709.416,417.91 ; 708.899,304.382 ccw(c707.021,306.26) 709.677,306.26 ccw(c712.333,306.26) 710.455,304.382 ; 709.111,304.17 ccw(c707.746,305.535) 709.677,305.535 ccw(c711.608,305.535) 710.243,304.17 ; 709.141,327.392 ccw(c708.921,327.688) 709.29,327.688 ; 709.244,327.171 cw(c709.732,327.38) 709.357,327.755 ; 709.29,326.21 709.29,326.591 709.29,327.688 ; 709.439,327.392 cw(c709.659,327.688) 709.29,327.688 ; 709.496,385.91 ccw(c709.496,388.093) v1@711.04,386.549 ; 709.52,327.289 cw(c710.173,327.567) 709.671,328.069 ; 709.536,332.785 cw(c709.098,332.347) 709.717,332.347 cw(c710.336,332.347) 709.898,332.785 ; 709.536,334.875 ccw(c708.178,336.232) 710.098,336.232 ; 709.677,303.604 709.677,307.715 709.971,308.009 732.558,308.009 734.584,310.035 738.394,310.035 739.354,310.995 739.354,332.154 738.796,332.712 734.889,332.712 ; 709.717,334.656 710.098,335.037 710.098,338.021 712.511,340.434 712.511,342.847 ; 709.748,334.663 ccw(c708.902,335.508) 710.098,335.508 ; 710.22,385.91 ccw(c710.22,387.369) v1@711.252,386.337 ; 710.677,383.723 ccw(c710.463,383.937) 710.765,383.937 ccw(c711.067,383.937) 710.853,383.723 ; 710.765,382.91 710.765,385.815 ; 710.898,386.125 ccw(c711.418,386.645) 711.418,385.91 ; 710.933,332.785 cw(c710.495,332.347) 711.114,332.347 cw(c711.733,332.347) 711.295,332.785 ; 710.933,334.875 ccw(c710.188,335.619) 711.241,335.619 ; 710.945,385.91 ccw(c710.945,386.645) 711.464,386.125 ; 711.1,336.368 cw(c710.758,336.026) 711.241,336.026 cw(c711.724,336.026) 711.382,336.368 ; v1@711.11,386.337 ccw(c712.142,387.369) 712.142,385.91 ; 711.241,334.783 711.241,337.259 ; v1@711.323,386.549 ccw(c712.866,388.093) 712.866,385.91 ; 712.33,332.785 cw(c711.892,332.347) 712.511,332.347 cw(c713.13,332.347) 712.692,332.785 ; 712.33,334.875 ccw(c711.892,335.313) 712.511,335.313 ccw(c713.13,335.313) 712.692,334.875 ; 712.37,336.368 cw(c712.028,336.026) 712.511,336.026 cw(c712.994,336.026) 712.652,336.368 ; 712.37,341.956 cw(c712.028,341.614) 712.511,341.614 cw(c712.994,341.614) 712.652,341.956 ; 712.511,334.656 712.511,337.259 ; 713.288,349.606 cw(c712.52,348.838) 713.606,348.838 cw(c714.692,348.838) 713.924,349.606 ; 713.64,336.368 cw(c713.298,336.026) 713.781,336.026 cw(c714.264,336.026) 713.922,336.368 ; 713.64,343.738 ccw(c713.298,344.08) 713.781,344.08 ccw(c714.264,344.08) 713.922,343.738 ; 713.727,332.785 cw(c713.289,332.347) 713.908,332.347 cw(c714.527,332.347) 714.089,332.785 ; 713.781,334.783 713.781,337.259 ; 713.781,335.619 ccw(c714.834,335.619) 714.089,334.875 ; 713.781,342.847 713.781,345.768 714.162,346.149 723.306,346.149 723.766,346.609 723.766,350.086 ; 713.908,333.005 713.908,328.623 713.354,328.069 709.671,328.069 ; 714.677,303.604 714.677,306.954 715.178,307.455 732.788,307.455 734.814,309.481 738.624,309.481 739.908,310.765 739.908,333.957 739.527,334.338 732.069,334.338 731.46,334.947 731.46,335.697 ; v1@714.783,354.136 cw(c714.441,353.794) 714.924,353.794 cw(c715.407,353.794) v1@715.065,354.136 ; v1@714.783,354.418 ccw(c714.441,354.76) 714.924,354.76 ccw(c715.407,354.76) v1@715.065,354.418 ; v1@714.783,354.771 cw(c714.441,354.429) 714.924,354.429 cw(c715.407,354.429) v1@715.065,354.771 ; 714.91,336.368 cw(c714.568,336.026) 715.051,336.026 cw(c715.534,336.026) 715.192,336.368 ; v1(714.924,354.912) 714.924,351.308 716.146,350.086 ; 715.051,334.91 715.051,337.259 ; 715.051,335.202 ccw(c715.813,335.202) 715.274,334.663 ; 715.051,335.926 ccw(c716.537,335.926) 715.486,334.875 ; 715.101,351.131 ccw(c716.146,352.176) 716.146,350.698 ; 715.124,332.785 cw(c714.686,332.347) 715.305,332.347 cw(c715.924,332.347) 715.486,332.785 ; 715.147,320.018 cw(c714.472,319.343) 715.427,319.343 ; 715.257,319.908 ccw(c715.777,320.428) 715.777,319.693 ; 715.305,333.005 715.305,328.496 715.749,328.052 716.765,328.052 716.902,327.915 716.902,326.616 ; 715.492,350.74 cw(c715.001,350.248) 715.696,350.248 ; 715.613,350.619 ccw(c716.146,351.151) 716.146,350.398 ; 715.677,382.097 cw(c715.463,381.883) 715.765,381.883 cw(c716.067,381.883) 715.853,382.097 ; 715.677,421.097 cw(c715.463,420.883) 715.765,420.883 cw(c716.067,420.883) 715.853,421.097 ; 715.713,353.059 ccw(c714.668,354.104) 716.146,354.104 ccw(c717.623,354.104) 716.579,353.059 ; 715.765,382.91 715.765,379.423 716.273,378.915 723.877,378.915 ; 715.765,417.958 715.765,421.91 ; 716.146,352.626 716.146,354.991 716.956,355.801 731.688,355.801 731.95,356.063 ; 716.18,336.368 cw(c715.838,336.026) 716.321,336.026 cw(c716.804,336.026) 716.462,336.368 ; 716.18,343.738 ccw(c715.838,344.08) 716.321,344.08 ccw(c716.804,344.08) 716.462,343.738 ; v1@716.18,344.103 cw(c715.838,343.761) 716.321,343.761 cw(c716.804,343.761) v1@716.462,344.103 ; 716.321,335.037 716.321,337.259 ; 716.321,335.508 ccw(c717.517,335.508) 716.671,334.663 ; 716.321,336.232 ccw(c718.241,336.232) 716.883,334.875 ; 716.321,342.847 v1(716.321,344.244) ; 716.521,332.785 cw(c716.083,332.347) 716.702,332.347 cw(c717.321,332.347) 716.883,332.785 ; 716.677,382.097 cw(c716.463,381.883) 716.765,381.883 cw(c717.067,381.883) 716.853,382.097 ; 716.702,333.005 716.702,329.893 716.702,328.732 716.829,328.605 717.744,328.605 718.362,327.988 718.362,326.21 ; 716.725,327.393 ccw(c716.298,327.82) 716.902,327.82 ccw(c717.505,327.82) 717.078,327.393 ; 716.765,382.91 716.765,380.63 717.083,380.312 723.877,380.312 ; 716.902,326.235 716.902,326.899 ; 717.45,336.368 cw(c717.108,336.026) 717.591,336.026 cw(c718.074,336.026) 717.732,336.368 ; 717.45,343.738 ccw(c717.108,344.08) 717.591,344.08 ccw(c718.074,344.08) 717.732,343.738 ; v1@717.45,345.119 cw(c717.108,344.777) 717.591,344.777 cw(c718.074,344.777) 717.732,345.119 cw(c718.074,344.777) 718.074,345.26 cw(c718.074,345.743) v1@717.732,345.401 ; 717.591,335.091 ccw(c718.496,335.091) 717.856,334.451 ; 717.591,335.815 ccw(c719.22,335.815) 718.068,334.663 ; 717.591,336.539 ccw(c719.944,336.539) 718.28,334.875 ; 717.591,337.259 717.591,335.164 718.099,334.656 ; 717.591,342.847 v1(717.591,345.26) 724.322,345.26 725.338,346.276 725.338,350.975 724.957,351.356 722.496,351.356 721.226,352.626 ; 717.61,335.144 ccw(c718.08,335.614) 718.094,334.95 ; 717.688,335.066 cw(c717.316,334.694) 717.843,334.694 ; 717.918,332.785 cw(c717.48,332.347) 718.099,332.347 cw(c718.718,332.347) 718.28,332.785 ; 718.074,350.086 ccw(c716.596,350.086) 717.641,351.131 ccw(c718.686,352.176) 718.686,350.698 ; 718.099,333.005 718.099,330.092 718.806,329.385 725.465,329.385 725.973,328.877 725.973,326.235 ; 718.185,327.368 ccw(c717.758,327.795) 718.362,327.795 ccw(c718.965,327.795) 718.538,327.368 ; 718.686,350.086 717.464,351.308 717.464,354.531 717.845,354.912 732.536,354.912 732.536,352.991 ; 718.686,352.014 cw(c718.686,350.536) 719.731,351.581 cw(c720.775,352.626) 719.298,352.626 ; 718.72,336.368 cw(c718.378,336.026) 718.861,336.026 cw(c719.344,336.026) 719.002,336.368 ; 718.861,337.259 718.861,335.608 ; 718.899,304.382 ccw(c717.021,306.26) 719.677,306.26 ccw(c722.333,306.26) 720.455,304.382 ; 719.111,304.17 ccw(c717.746,305.535) 719.677,305.535 ccw(c721.608,305.535) 720.243,304.17 ; 719.24,334.694 ccw(c717.946,334.694) 718.861,335.608 ; 719.315,332.785 cw(c718.877,332.347) 719.496,332.347 cw(c720.115,332.347) 719.677,332.785 ; 719.373,335.096 cw(c718.97,334.694) 719.54,334.694 ; 719.496,333.005 719.496,330.393 719.869,330.02 726.608,330.02 727.433,329.195 727.433,326.21 ; 719.496,334.656 719.496,334.973 718.861,335.608 ; 719.628,385.91 688.635,385.91 ; 719.677,383.723 ccw(c719.463,383.937) 719.765,383.937 ccw(c720.067,383.937) 719.853,383.723 ; 719.677,303.604 719.677,306.447 720.131,306.901 733.017,306.901 735.043,308.927 738.853,308.927 740.462,310.536 740.462,335.227 739.992,335.697 ; 719.765,382.91 719.765,417.91 ; 719.765,386.201 cw(c720.63,386.201) v1@720.018,386.813 ; 719.765,387.707 ccw(c720.63,387.707) v1@720.018,387.096 ; 719.765,412.31 cw(c721.064,412.31) v1@720.145,413.229 ; 719.765,413.035 cw(c720.34,413.035) v1@719.933,413.441 ; 719.765,413.706 ccw(c720.34,413.706) v1@719.933,413.299 ; 719.765,414.43 ccw(c721.064,414.43) v1@720.145,413.512 ; 719.805,399.91 723.765,399.91 727.139,399.91 ; 719.822,390.91 723.765,390.91 ; 719.866,384.91 723.765,384.91 ; 719.87,387.91 723.765,387.91 ; 719.915,408.91 723.765,408.91 ; 720.677,382.097 cw(c720.463,381.883) 720.765,381.883 cw(c721.067,381.883) 720.853,382.097 ; 720.765,382.91 720.765,381.583 721.02,381.328 738.419,381.328 739.332,380.415 739.332,338.886 739.816,338.402 745.023,338.402 745.404,338.021 745.404,317.955 ; 720.793,349.653 cw(c719.748,348.609) 721.226,348.609 cw(c722.703,348.609) 721.659,349.653 ; v1(721.02,344.498) 722.163,344.498 ; v1@721.161,344.357 cw(c721.503,344.015) 721.503,344.498 cw(c721.503,344.981) v1@721.161,344.639 ; 721.226,352.014 cw(c721.226,350.536) 722.271,351.581 cw(c723.315,352.626) 721.838,352.626 ; 721.765,382.91 721.765,382.107 739.164,382.107 739.886,381.385 739.886,339.348 740.197,339.037 748.198,339.037 748.452,338.783 v1(748.452,325.575) ; 721.853,382.273 ccw(c722.255,382.675) 722.255,382.107 ; 721.982,342.749 ccw(c721.544,343.187) 722.163,343.187 ccw(c722.782,343.187) 722.344,342.749 ; 722.099,340.815 v1(723.306,340.815) 723.306,343.482 723.814,343.99 727.116,343.99 727.687,344.562 727.687,349.485 728.669,350.467 ; 722.163,342.657 722.163,344.498 ; 722.344,340.659 cw(c722.721,340.283) 722.721,340.815 ; 722.344,341.022 ccw(c722.843,341.521) 722.843,340.815 ; 722.952,384.822 ccw(c722.738,384.608) 722.738,384.91 ccw(c722.738,385.212) 722.952,384.998 ; 722.952,387.822 ccw(c722.738,387.608) 722.738,387.91 ccw(c722.738,388.212) 722.952,387.998 ; 722.952,390.822 ccw(c722.738,390.608) 722.738,390.91 ccw(c722.738,391.212) 722.952,390.998 ; 722.952,399.822 ccw(c722.738,399.608) 722.738,399.91 ccw(c722.738,400.212) 722.952,399.998 ; 722.952,408.822 ccw(c722.738,408.608) 722.738,408.91 ccw(c722.738,409.212) 722.952,408.998 ; 722.952,417.822 ccw(c722.738,417.608) 722.738,417.91 ccw(c722.738,418.212) 722.952,417.998 ; v1@723.165,340.674 ccw(c722.823,340.332) 722.823,340.815 ccw(c722.823,341.298) 723.165,340.956 ccw(c722.823,341.298) 723.306,341.298 ccw(c723.789,341.298) v1@723.447,340.956 ; 723.333,349.653 cw(c722.288,348.609) 723.766,348.609 cw(c725.243,348.609) 724.199,349.653 ; 723.658,375.432 ccw(c723.22,374.994) 723.22,375.613 ccw(c723.22,376.232) 723.658,375.794 ; 723.658,376.829 ccw(c723.22,376.391) 723.22,377.01 ccw(c723.22,377.629) 723.658,377.191 ; 723.658,378.734 ccw(c723.22,378.296) 723.22,378.915 ccw(c723.22,379.534) 723.658,379.096 ; 723.658,380.131 ccw(c723.22,379.693) 723.22,380.312 ccw(c723.22,380.931) 723.658,380.493 ; 723.766,352.626 725.592,352.626 726.1,352.118 726.1,345.006 725.638,344.544 722.209,344.544 722.163,344.498 ; 723.765,385.91 739.552,385.91 740.44,385.022 740.44,341.035 741.214,340.261 742.737,340.261 743.037,340.261 743.637,340.261 743.856,340.261 744.156,340.261 744.756,340.261 745.356,340.261 745.356,339.661 745.956,339.661 745.956,340.261 748.071,340.261 750.784,340.261 751.073,339.972 751.073,315.969 751.546,315.496 753.713,315.496 754.044,315.165 754.044,310.585 ; 723.765,386.91 740.457,386.91 740.994,386.373 740.994,341.301 741.48,340.815 743.245,340.815 743.545,340.815 744.145,340.815 744.456,340.815 744.756,340.815 745.356,340.815 745.356,341.415 745.956,341.415 745.956,340.815 746.556,340.815 746.556,341.415 747.156,341.415 747.156,340.815 747.817,340.815 751.119,340.815 751.627,340.307 751.627,316.812 752.262,316.177 754.548,316.177 755.314,315.411 755.314,313.125 ; 723.765,388.91 740.489,388.91 741.548,387.851 741.548,342.639 742.102,342.085 748.96,342.085 v1(749.468,341.577) ; 723.765,389.91 741.14,389.91 742.102,388.948 742.102,343.482 742.61,342.974 743.753,342.974 744.053,342.974 744.053,343.65 744.653,343.65 744.653,342.974 746.039,342.974 747.69,342.974 749.468,342.974 v1(750.23,342.212) ; 723.765,406.91 726.045,406.91 726.354,406.601 726.354,405.204 726.735,404.823 728.513,404.823 ; 723.765,407.91 725.885,407.91 726.354,408.379 726.354,409.522 726.735,409.903 728.513,409.903 ; 723.765,417.91 719.765,417.91 ; 724.199,352.193 cw(c725.243,351.149) 725.243,352.626 cw(c725.243,354.104) 724.199,353.059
